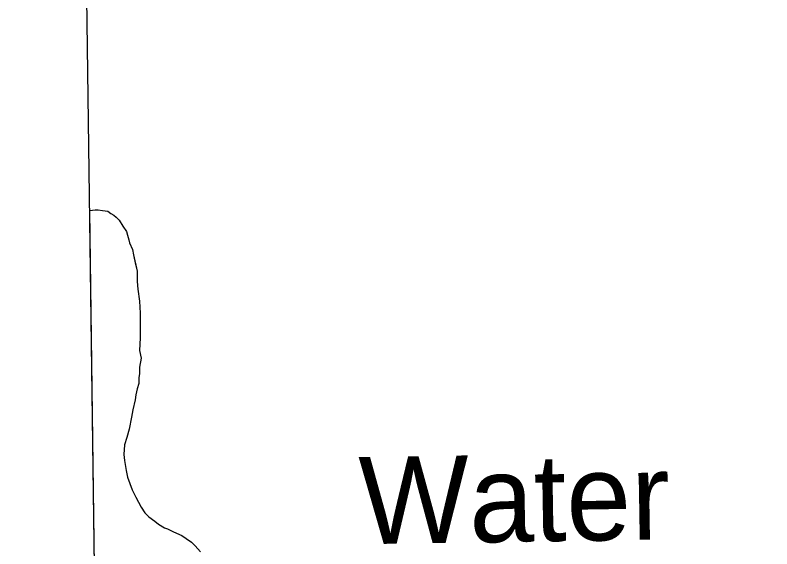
# Model space of a CAD drawing. Extents: x 3767014 to 3805179, y 361544 to 387384.
# Drawn here: x 3771007 to 3771875, y 378392 to 379004 of the extents above; entities that cross this region are included whole.
import ezdxf

# ---------------------------------------------------------------- set-up
doc = ezdxf.new("R2010")
doc.units = 0
for name, color, linetype in [('V-GRID-FRAM', 7, 'Continuous'), ('V-RIVR-IDEN', 7, 'Continuous'), ('V-TOPO-SHOR', 7, 'Continuous'), ('V-WETL-SWMP', 7, 'Continuous')]:
    doc.layers.add(name, color=color, linetype=linetype)

msp = doc.modelspace()

# ---------------------------------------------------------------- linework, layer by layer
at = {"layer": 'V-GRID-FRAM'}
msp.add_lwpolyline([(3771006.872, 385146.094), (3802799.803, 385587.734), (3803060.286, 367407.215), (3771251.489, 366965.353), (3771006.872, 385146.094)], dxfattribs=at)
at = {"layer": 'V-TOPO-SHOR'}
for points in [[(3771092.524, 378780.152), (3771098.621, 378780.839), (3771102.06, 378780.843), (3771107.217, 378779.989), (3771113.232, 378779.137), (3771116.672, 378776.563), (3771120.111, 378774.848), (3771122.694, 378772.274), (3771126.134, 378768.84), (3771130.439, 378761.971), (3771134.744, 378755.96), (3771135.608, 378751.665), (3771137.335, 378746.51), (3771138.199, 378743.074), (3771141.644, 378735.344), (3771142.51, 378729.33), (3771145.103, 378718.162)], [(3771145.103, 378718.162), (3771146.831, 378710.429), (3771146.846, 378698.399), (3771147.714, 378689.805), (3771149.451, 378676.057), (3771150.327, 378662.309), (3771150.333, 378657.152), (3771150.348, 378644.262), (3771150.36, 378633.948), (3771149.518, 378619.34), (3771151.249, 378610.748), (3771149.543, 378600.432), (3771149.551, 378592.699), (3771148.697, 378588.4), (3771148.705, 378581.525), (3771146.993, 378575.508), (3771145.283, 378568.631), (3771144.431, 378562.614), (3771141.867, 378551.44), (3771140.159, 378542.845), (3771137.599, 378529.09), (3771135.031, 378519.635), (3771132.463, 378511.039), (3771131.617, 378499.865), (3771132.485, 378492.992), (3771134.218, 378481.823), (3771135.944, 378474.089), (3771141.119, 378459.487), (3771145.426, 378450.9), (3771151.456, 378439.734), (3771155.761, 378432.865), (3771160.063, 378428.573), (3771166.945, 378423.426), (3771171.246, 378419.993), (3771178.125, 378415.705), (3771181.563, 378414.849), (3771188.443, 378411.421), (3771197.9, 378407.134), (3771203.061, 378403.704), (3771209.082, 378399.413), (3771213.383, 378395.123), (3771219.408, 378388.256)]]:
    msp.add_lwpolyline(points, dxfattribs=at)
at = {"layer": 'V-WETL-SWMP'}
for p, q in [((3771092.524, 378780.153), (3771098.621, 378780.838)), ((3771105.597, 377808.528), (3771092.524, 378780.153)), ((3771098.621, 378780.838), (3771102.059, 378780.842)), ((3771102.059, 378780.842), (3771107.216, 378779.989)), ((3771107.216, 378779.989), (3771113.232, 378779.137)), ((3771113.232, 378779.137), (3771116.673, 378776.563)), ((3771116.673, 378776.563), (3771120.112, 378774.849)), ((3771120.112, 378774.849), (3771126.135, 378768.84)), ((3771126.135, 378768.84), (3771130.44, 378761.971)), ((3771130.44, 378761.971), (3771134.745, 378755.96)), ((3771134.745, 378755.96), (3771135.609, 378751.665)), ((3771135.609, 378751.665), (3771137.334, 378746.51)), ((3771137.334, 378746.51), (3771138.198, 378743.074)), ((3771138.198, 378743.074), (3771141.644, 378735.344)), ((3771141.644, 378735.344), (3771142.511, 378729.329)), ((3771142.511, 378729.329), (3771146.831, 378710.429)), ((3771146.831, 378710.429), (3771146.845, 378698.398)), ((3771146.845, 378698.398), (3771147.715, 378689.805)), ((3771147.715, 378689.805), (3771149.451, 378676.057)), ((3771149.451, 378676.057), (3771150.327, 378662.308)), ((3771150.327, 378662.308), (3771150.361, 378633.949)), ((3771150.361, 378633.949), (3771149.519, 378619.339)), ((3771149.519, 378619.339), (3771151.248, 378610.748)), ((3771151.248, 378610.748), (3771149.542, 378600.433)), ((3771149.542, 378600.433), (3771149.552, 378592.699)), ((3771149.552, 378592.699), (3771148.697, 378588.401)), ((3771148.706, 378581.526), (3771146.994, 378575.509)), ((3771148.697, 378588.401), (3771148.706, 378581.526)), ((3771146.994, 378575.509), (3771145.284, 378568.632)), ((3771145.284, 378568.632), (3771144.432, 378562.615)), ((3771144.432, 378562.615), (3771141.867, 378551.44)), ((3771141.867, 378551.44), (3771140.159, 378542.844)), ((3771140.159, 378542.844), (3771137.598, 378529.091)), ((3771137.598, 378529.091), (3771135.031, 378519.635)), ((3771135.031, 378519.635), (3771132.463, 378511.039)), ((3771132.463, 378511.039), (3771131.617, 378499.866)), ((3771131.617, 378499.866), (3771132.485, 378492.992)), ((3771132.485, 378492.992), (3771134.217, 378481.822)), ((3771134.217, 378481.822), (3771135.945, 378474.09)), ((3771135.945, 378474.09), (3771141.119, 378459.487)), ((3771141.119, 378459.487), (3771145.427, 378450.899)), ((3771145.427, 378450.899), (3771151.456, 378439.734)), ((3771151.456, 378439.734), (3771155.761, 378432.865)), ((3771155.761, 378432.865), (3771160.063, 378428.573)), ((3771160.063, 378428.573), (3771166.944, 378423.425)), ((3771166.944, 378423.425), (3771171.245, 378419.993)), ((3771171.245, 378419.993), (3771178.125, 378415.704)), ((3771178.125, 378415.704), (3771181.564, 378414.849)), ((3771181.564, 378414.849), (3771188.443, 378411.42)), ((3771188.443, 378411.42), (3771197.901, 378407.135)), ((3771197.901, 378407.135), (3771203.061, 378403.703)), ((3771203.061, 378403.703), (3771209.082, 378399.414)), ((3771209.082, 378399.414), (3771213.384, 378395.122)), ((3771213.384, 378395.122), (3771219.408, 378388.255))]:
    msp.add_line(p, q, dxfattribs=at)

# ---------------------------------------------------------------- texts
at = {"layer": 'V-RIVR-IDEN'}
msp.add_text('Water', height=100, rotation=0.919589, dxfattribs=at).set_placement((3771401.992, 378396.974))

doc.saveas('drawing.dxf')
